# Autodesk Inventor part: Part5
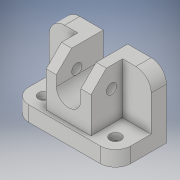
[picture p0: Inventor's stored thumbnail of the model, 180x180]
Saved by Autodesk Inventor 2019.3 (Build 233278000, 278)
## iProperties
Created: 2019-02
Part Number: Part5
Material: Generic
Document SubType Name: Modeling
Designer: Synergysoft
Density: 1 g/cm^3
Appearance: Default
Author: Synergysoft
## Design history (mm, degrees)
sketch "Sketch1"
  geometry: L1 (0, 0)-(0, 50); L2 (0, 50)-(15, 50); L3 (15, 50)-(15, 15); L4 (15, 15)-(65, 15); L5 (65, 15)-(65, 0); L6 (65, 0)-(0, 0)
  constraints: 12 end point, 4 perpendicular, 1 vertical
  dimensions: "d0" = 50 distance of L1.start L1.end; "d1" = 15 distance of L1.end L2.end; "d2" = 35 distance of L2.end L3.end; "d3" = 50 distance of L3.end L4.end; "d4" = 15 distance of L4.end L5.end
extrude "Extrusion1" new body sketch "Sketch1" distance "d5" = 100; taper "d6" = 0 deg
sketch "Sketch2"
  geometry: L1 (28, 50)-(72, 50); L2 (72, 50)-(72, 0); L3 (72, 0)-(28, 0); L4 (28, 0)-(28, 50); L5 (0, 0)-(0, 50) reference; L6 (0, 0)-(100, 0) reference; L7 (100, 50)-(100, 0) reference; L8 (0, 50)-(100, 50) reference; 3 further points
  constraints: 8 end point, 4 midpoint, 2 parallel, 1 horizontal, 1 perpendicular
  dimensions: "d7" = 44 distance between parallel lines of L2 L4
extrude "Extrusion2" join sketch "Sketch2" distance "d8" = 31; taper "d9" = 0 deg
sketch "Sketch3"
  geometry: L1 (50, 25)-(50, 75); L2 (38, 25)-(38, 75); L3 (62, 75)-(62, 25); L4 (72, 50)-(28, 50) reference; A1 r 12 centre (50, 25) between (38, 25) and (62, 25); A2 r 12 centre (50, 75) between (62, 75) and (38, 75); 2 further points
  constraints: 8 end point, 4 point on circle, 4 tangent, 2 centre point, 2 midpoint, 1 parallel, 1 vertical
  dimensions: "d10" = 12 radius of A1; "d11" = 25 distance from line of L4 L1.start
extrude "Extrusion3" cut sketch "Sketch3" extent not by distance; stored distance "d12" = 20; taper "d13" = 0 deg
chamfer "Chamfer1" distance "d14" = 15; stored, may be unused: second distance "d15" = 15, angle "d16" = 60 deg
fillet "Fillet1" dims "d17" = 15
sketch "Sketch4"
  geometry: L1 (-20, -15)-(15, -15) reference; L2 (15, -15)-(15, 35) reference; 1 further point
  dimensions: "d18" = 45 distance from line of L1 point (-11, 30); "d19" = 26 distance from line of L2 point (-11, 30)
hole "Hole1" sketch "Sketch4" at (-11, 30) diameter "d20" = 10; stored, may be unused: countersink angle "d24" = 90 deg, drill point angle "d26" = 118 deg; dims "d21" = 6, "d22" = 4, "d23" = 2, "d25" = 8
sketch "Sketch5"
  geometry: A1 r 15 centre (57, 11) between (57, -4) and (72, 11) reference; A2 r 15 centre (-13, 11) between (-28, 11) and (-13, -4) reference; 3 further points
  constraints: 2 coincident
hole "Hole2" sketch "Sketch5" at (57, 11), (-13, 11) diameter "d27" = 7; stored, may be unused: countersink angle "d31" = 90 deg, drill point angle "d33" = 118 deg; dims "d28" = 6, "d29" = 11, "d30" = 7, "d32" = 8
body "Solid1"
node "Projected Loop1"
